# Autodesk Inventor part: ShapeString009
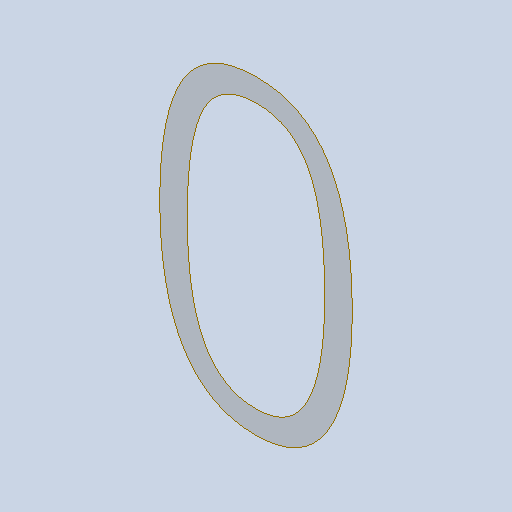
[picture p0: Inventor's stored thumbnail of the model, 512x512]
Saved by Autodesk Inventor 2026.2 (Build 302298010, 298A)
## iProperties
Created: 2026-10
Part Number: ShapeString009
Material: Générique
Document SubType Name: Modeling
Designer: mel
Density: 1 g/cm^3
Appearance: Par défaut
Author: mel
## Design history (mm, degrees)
feature "Composite1"
body "Srf1"
